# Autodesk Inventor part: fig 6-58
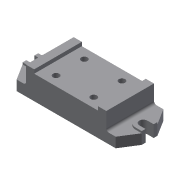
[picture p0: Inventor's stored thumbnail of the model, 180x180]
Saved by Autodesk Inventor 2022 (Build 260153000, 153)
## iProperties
Created: 2001-12
Part Number: fig 6-58
Document SubType Name: Modeling
Designer: Renu Muthoo
Density: 1 g/cm^3
Material: Generic
Appearance: Default
Control State: 0
Master: False
Checked Out: False
Shininess: 77.0
Angle Display Precision: 2
Document Length Units: 11269
Document Angle Units: 11279
Document Time Units: 11290
Document Mass Units: 11283
Document Length Units Precision: 3
Document Angle Units Precision: 2
Density: 0.0
Volumn: 0.0
Area: 0.0
PropertySet Name: Model Information
Author: Renu Muthoo
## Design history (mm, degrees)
sketch "Sketch3"
  geometry: L1 (-59.119, -24.322)-(-59.119, 19.678); L2 (-59.119, 19.678)-(-46.119, 19.678); L3 (-46.119, 19.678)-(-46.119, 13.678); L4 (-46.119, 13.678)-(55.881, 13.678); L5 (55.881, 13.678)-(55.881, 19.678); L6 (55.881, 19.678)-(68.881, 19.678); L7 (68.881, 19.678)-(68.881, -24.322); L8 (68.881, -24.322)-(-59.119, -24.322)
  constraints: 16 end point, 2 equal length
  dimensions: "d10" = 13 distance of L1.end L2.end; "d11" = 102 distance of L3.end L4.end; "d13" = 44 distance between parallel lines of L2 L8; "d14" = 6 distance of L2.end L3.end
extrude "Extrusion1" new body sketch "Sketch3" distance "d15" = 76; taper "d16" = 0 deg
sketch "Sketch4"
  geometry: L1 (0, 0)-(0, 76) reference; L2 (0, 76)-(-15, 76); L3 (-15, 76)-(-31, 50.5); L4 (-31, 50.5)-(-31, 44.5); L5 (-31, 44.5)-(-21, 44.5); L6 (-21, 31.5)-(-31, 31.5); L7 (-31, 31.5)-(-31, 25.5); L8 (-31, 25.5)-(-15, 0); L9 (-15, 0)-(0, 0); L10 (128, 76)-(0, 76) reference; L11 (0, 0)-(128, 0) reference; A1 r 6.5 centre (-21, 38) between (-21, 31.5) and (-21, 44.5)
  constraints: 16 end point, 4 equal length, 3 collinear, 3 parallel, 2 perpendicular, 2 point on circle, 2 tangent, 1 centre point
  dimensions: "d17" = 13 distance between parallel lines of L6 L5; "d18" = 25 distance of L3.end L7.end; "d19" = 10 distance of L6.start L6.end; "d20" = 15 distance of L8.end L1.start; "d21" = 16 horizontal distance of L7.end L8.end
extrude "Extrusion2" join sketch "Sketch4" distance "d22" = 16; taper "d23" = 0 deg
sketch "Sketch5"
  geometry: L1 (-159, 44.5)-(-159, 50.5) reference; L2 (-149, 44.5)-(-159, 44.5) reference; L3 (-159, 31.5)-(-149, 31.5) reference; L4 (-159, 25.5)-(-159, 31.5) reference; L5 (-159, 25.5)-(-149, 25.5); L6 (-149, 50.5)-(-159, 50.5); A1 r 6.5 centre (-149, 38) between (-149, 31.5) and (-149, 44.5) reference; A2 r 12.5 centre (-149, 38) between (-149, 25.5) and (-149, 50.5)
  constraints: 4 end point, 2 point on circle, 2 tangent, 1 centre point, 1 parallel, 1 perpendicular
extrude "Extrusion3" join sketch "Sketch5" distance "d24" = 19; taper "d25" = 0 deg
workplane "Work Plane1"
mirror "Mirror1"
fillet "Fillet1" dims "d27" = 4
sketch "Sketch6"
  geometry: L1 (0, 0)-(0, 76) reference; L2 (0, 0)-(102, 0) reference; 1 further point
  dimensions: "d28" = 20 distance from line of L1 point (20, 15); "d29" = 15 distance from line of L2 point (20, 15)
hole "Hole1" sketch "Sketch6" at (20, 15) diameter "d30" = 10; stored, may be unused: countersink angle "d34" = 82 deg, drill point angle "d36" = 118 deg; dims "d31" = 6, "d32" = 4, "d33" = 2, "d35" = 15
sketch "Sketch7"
  geometry: C1 r 5 at (20, 15) reference; 3 further points
  constraints: 4 other
pattern_linear "Rectangular Pattern2" dims "d45" = 45, "d48" = 60
body "Solid1"
other parameters: "d26" = -64
